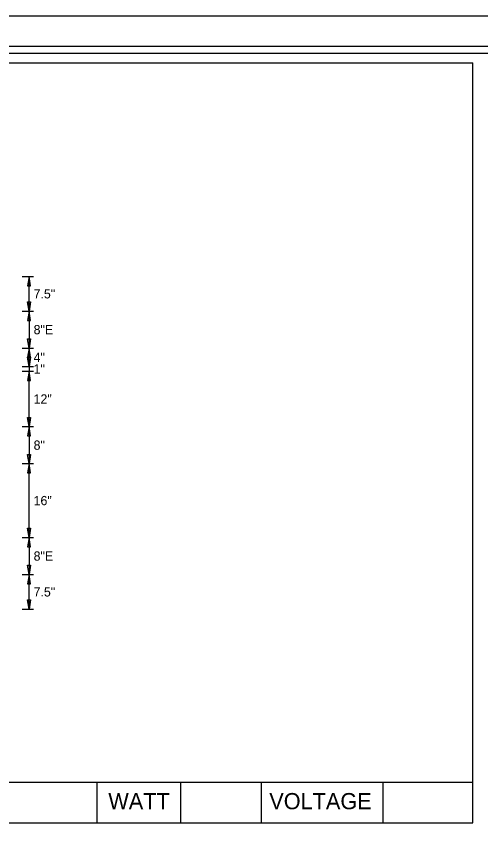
# Model space of a CAD drawing. Extents: x 1274.1 to 1363.1, y 833.5 to 890.6.
# Drawn here: x 1310.1 to 1318.48, y 875.95 to 890.63 of the extents above; entities that cross this region are included whole.
import ezdxf

# ---------------------------------------------------------------- set-up
doc = ezdxf.new("R2010")
doc.units = 0
for name, color, linetype in [('GSDims', 7, 'Continuous'), ('PlotBorder_dp', 7, 'Continuous'), ('SheetBorder_dp', 7, 'Continuous'), ('SheetLinesMisc2_dp', 7, 'Continuous'), ('TextMinor', 7, 'Continuous')]:
    doc.layers.add(name, color=color, linetype=linetype)

msp = doc.modelspace()

# ---------------------------------------------------------------- linework, layer by layer
at = {"layer": 'GSDims'}
for p, q in [((1310.208, 885.942), (1310.416, 885.942)), ((1310.208, 885.942), (1310.208, 885.942)), ((1310.333, 885.317), (1310.333, 885.942)), ((1310.208, 885.317), (1310.416, 885.317)), ((1310.208, 885.317), (1310.416, 885.317)), ((1310.333, 885.317), (1310.333, 884.65)), ((1310.208, 884.65), (1310.416, 884.65)), ((1310.208, 884.65), (1310.416, 884.65)), ((1310.333, 884.317), (1310.333, 884.65)), ((1310.208, 884.317), (1310.416, 884.317)), ((1310.208, 884.317), (1310.416, 884.317)), ((1310.333, 884.317), (1310.333, 884.234)), ((1310.208, 884.234), (1310.416, 884.234)), ((1310.208, 884.234), (1310.416, 884.234)), ((1310.333, 883.234), (1310.333, 884.234)), ((1310.208, 883.234), (1310.416, 883.234)), ((1310.208, 883.234), (1310.416, 883.234)), ((1310.333, 883.234), (1310.333, 882.567)), ((1310.208, 882.567), (1310.416, 882.567)), ((1310.208, 882.567), (1310.416, 882.567)), ((1310.333, 881.233), (1310.333, 882.567)), ((1310.208, 881.233), (1310.416, 881.233)), ((1310.208, 881.233), (1310.416, 881.233)), ((1310.333, 881.233), (1310.333, 880.567)), ((1310.208, 880.567), (1310.416, 880.567)), ((1310.208, 880.567), (1310.416, 880.567)), ((1310.333, 879.942), (1310.333, 880.567)), ((1310.208, 879.942), (1310.416, 879.942)), ((1310.208, 879.942), (1310.208, 879.942))]:
    msp.add_line(p, q, dxfattribs=at)
for points in [[(1310.333, 885.942), (1310.305, 885.775), (1310.361, 885.775)], [(1310.333, 885.317), (1310.305, 885.484), (1310.361, 885.484)], [(1310.333, 885.317), (1310.305, 885.15), (1310.361, 885.15)], [(1310.333, 884.65), (1310.305, 884.817), (1310.361, 884.817)], [(1310.333, 884.65), (1310.305, 884.484), (1310.361, 884.484)], [(1310.333, 884.317), (1310.305, 884.484), (1310.361, 884.484)], [(1310.333, 884.234), (1310.305, 884.067), (1310.361, 884.067)], [(1310.333, 883.234), (1310.305, 883.4), (1310.361, 883.4)], [(1310.333, 883.234), (1310.305, 883.067), (1310.361, 883.067)], [(1310.333, 882.567), (1310.305, 882.734), (1310.361, 882.734)], [(1310.333, 882.567), (1310.305, 882.4), (1310.361, 882.4)], [(1310.333, 881.233), (1310.305, 881.4), (1310.361, 881.4)], [(1310.333, 881.233), (1310.305, 881.067), (1310.361, 881.067)], [(1310.333, 880.567), (1310.305, 880.733), (1310.361, 880.733)], [(1310.333, 880.567), (1310.305, 880.4), (1310.361, 880.4)], [(1310.333, 879.942), (1310.305, 880.109), (1310.361, 880.109)]]:
    msp.add_lwpolyline(points, close=True, dxfattribs=at)
at = {"layer": 'PlotBorder_dp'}
msp.add_lwpolyline([(1274.135, 833.481), (1363.097, 833.481), (1363.097, 890.634), (1274.135, 890.634)], close=True, dxfattribs=at)
at = {"layer": 'SheetBorder_dp'}
msp.add_line((1277.101, 890.095), (1360.132, 890.095), dxfattribs=at)
at = {"layer": 'SheetLinesMisc2_dp'}
for p, q in [((1277.247, 889.967), (1359.988, 889.967)), ((1290.196, 889.796), (1318.336, 889.796)), ((1318.336, 876.088), (1318.336, 889.796)), ((1290.196, 876.823), (1318.336, 876.823)), ((1311.554, 876.823), (1311.554, 876.088)), ((1313.064, 876.823), (1313.064, 876.088)), ((1314.519, 876.823), (1314.519, 876.088)), ((1316.711, 876.823), (1316.711, 876.088)), ((1290.196, 876.088), (1318.336, 876.088))]:
    msp.add_line(p, q, dxfattribs=at)

# ---------------------------------------------------------------- texts
at = {"layer": 'GSDims'}
for s, p in [('7.5"', (1310.416, 885.546)), ('8"E', (1310.416, 884.9)), ('4"', (1310.416, 884.4)), ('1"', (1310.416, 884.192)), ('12"', (1310.416, 883.65)), ('8"', (1310.416, 882.817)), ('16"', (1310.416, 881.817)), ('8"E', (1310.416, 880.817)), ('7.5"', (1310.416, 880.171))]:
    msp.add_text(s, height=0.1667, dxfattribs=at).set_placement(p)
at = {"layer": 'TextMinor'}
for s, p in [('WATT', (1311.763, 876.334)), ('VOLTAGE', (1314.665, 876.334))]:
    msp.add_text(s, height=0.2923, dxfattribs=at).set_placement(p)

doc.saveas('drawing.dxf')
